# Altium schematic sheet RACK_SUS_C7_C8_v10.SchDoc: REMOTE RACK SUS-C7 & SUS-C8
size C; Engineer: L. Sanchez; Organization: LIGO Laboratory; Address1: California Institute of Technology; Address2: Massachusetts Institute of Technology; DocumentNumber: D1002740; Revision: v10; SheetNumber: 8; SheetTotal: 8
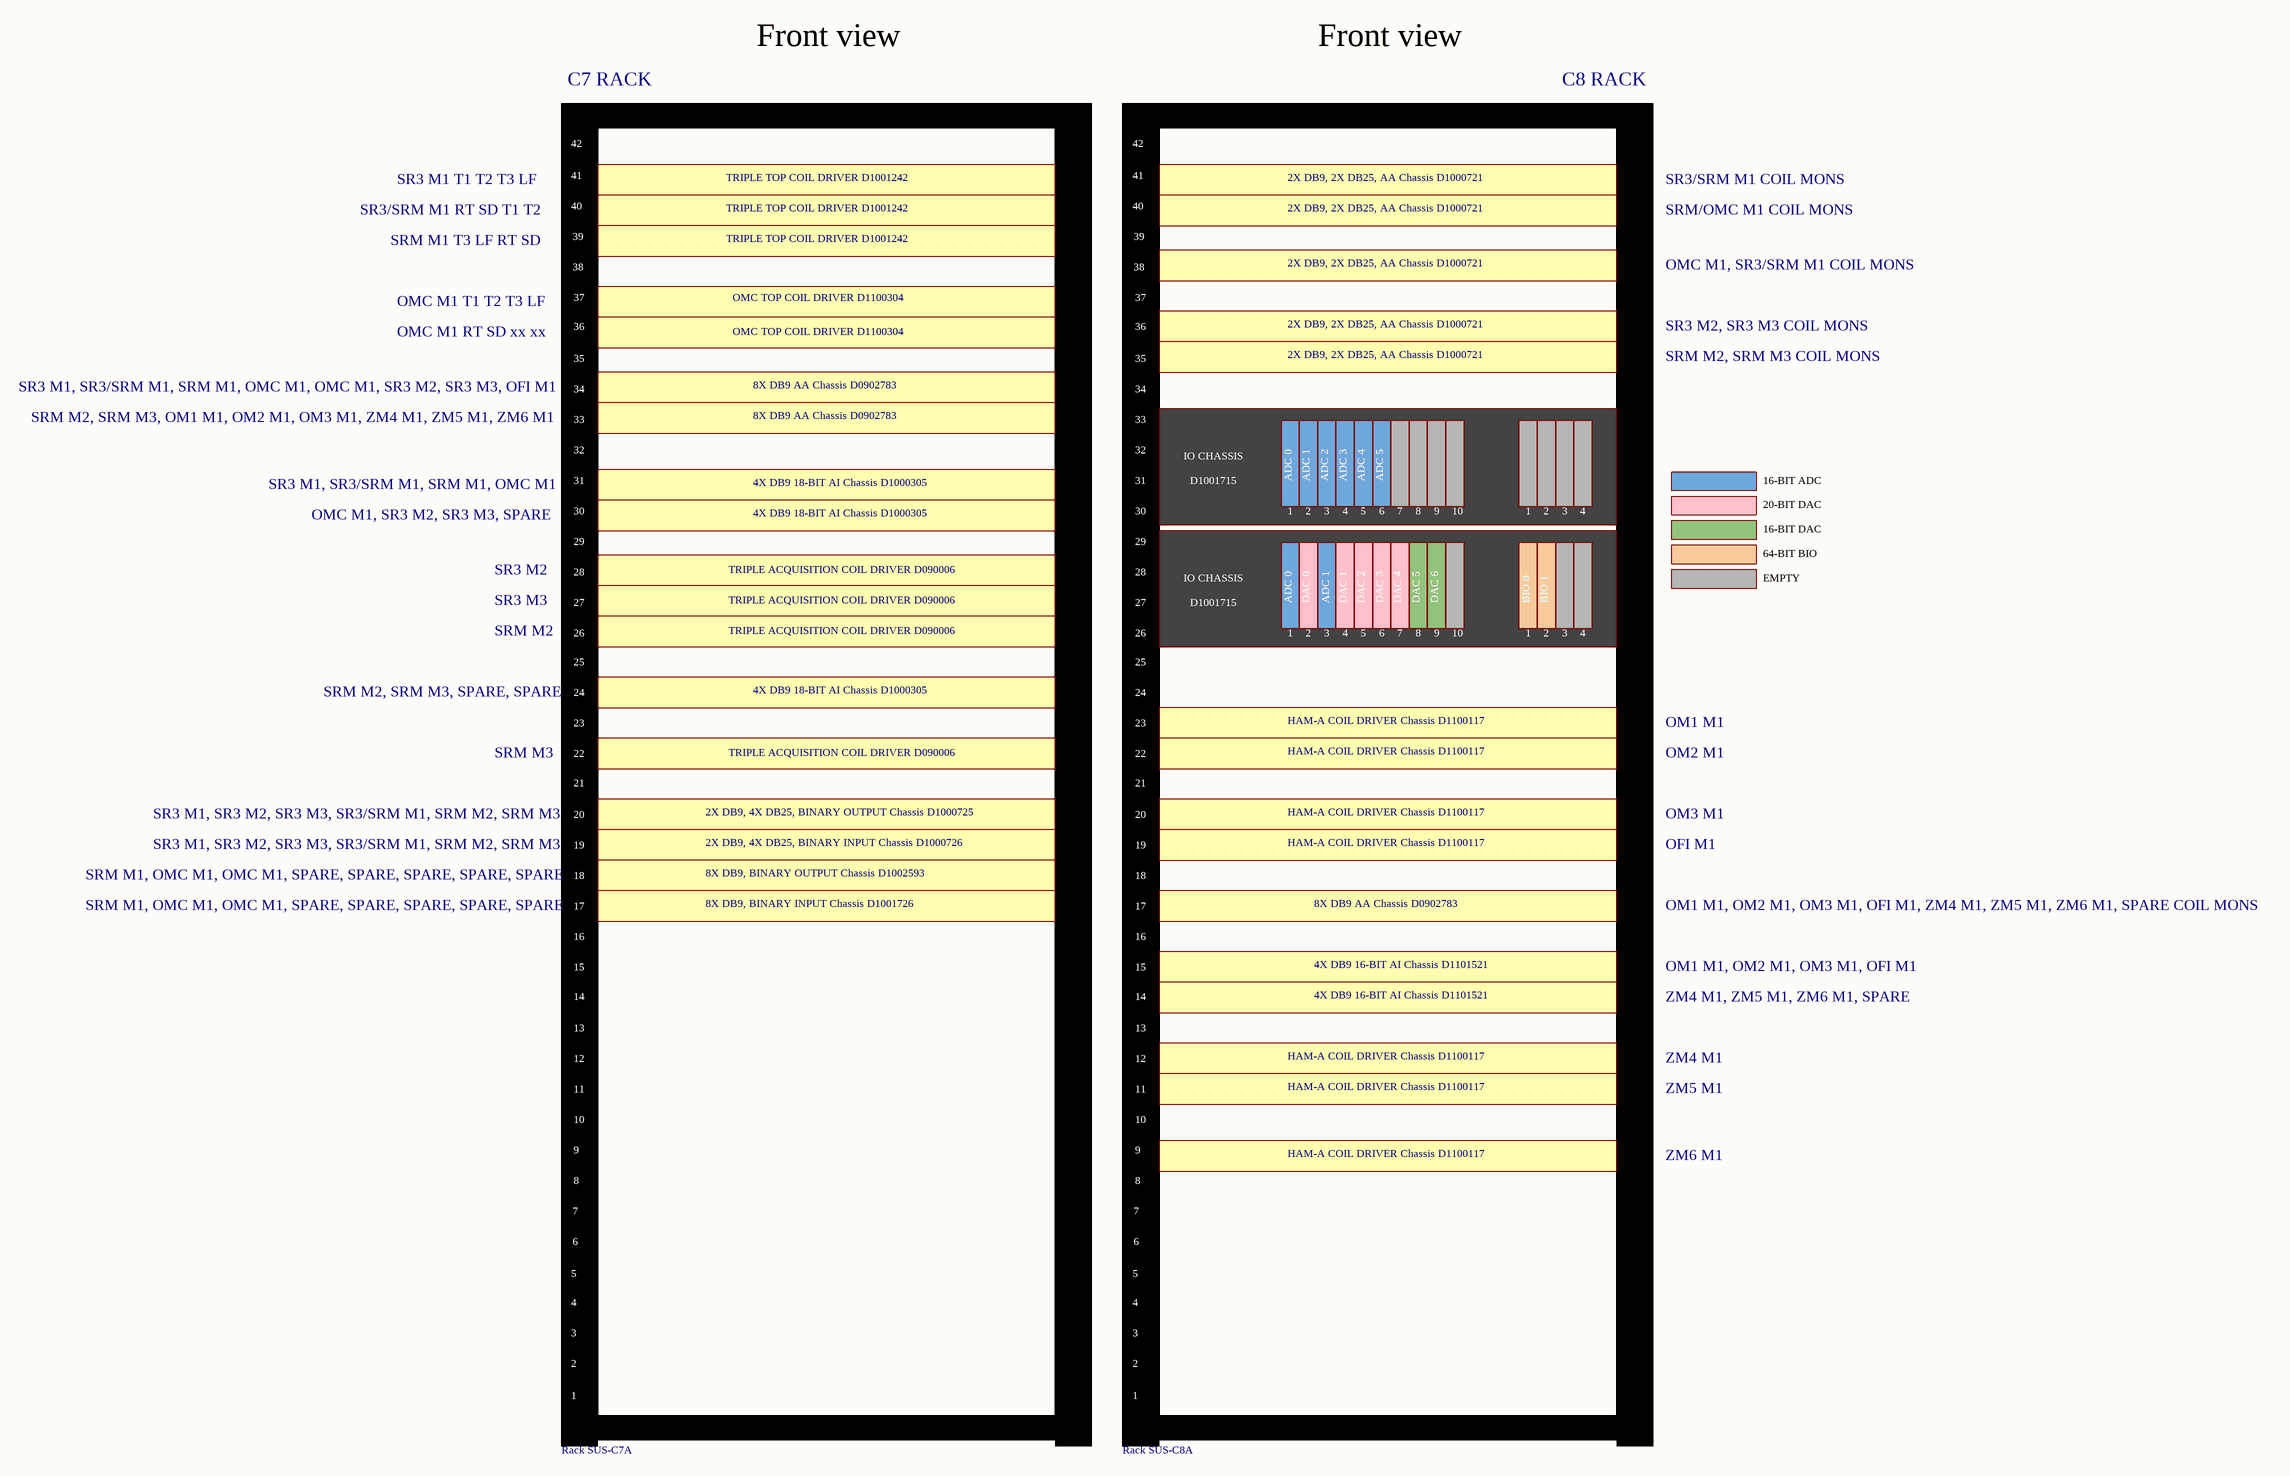
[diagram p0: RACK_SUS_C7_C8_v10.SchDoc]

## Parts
Rack_SUS-C7  1U  Rack 42 pos  (value not drawn)  (part A of 2)
Rack_SUS-C8  1U  Rack 42 pos  (value not drawn)  (part A of 2)

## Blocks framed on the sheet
2X DB9, 4X DB25, BINARY OUTPUT Chassis D1000725: Rack_SUS-C7
HAM-A COIL DRIVER Chassis D1100117: Rack_SUS-C8

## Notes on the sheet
- Front view
- C7 RACK
- C8 RACK
- SR3 M1 T1 T2 T3 LF
- TRIPLE TOP COIL DRIVER D1001242
- 2X DB9, 2X DB25, AA Chassis D1000721
- SR3/SRM M1 COIL MONS
- SR3/SRM M1 RT SD T1 T2
- SRM M1 T3 LF RT SD
- SRM/OMC M1 COIL MONS
- OMC M1 T1 T2 T3 LF
- OMC TOP COIL DRIVER D1100304
- OMC M1, SR3/SRM M1 COIL MONS
- OMC M1 RT SD xx xx
- SR3 M2, SR3 M3 COIL MONS
- SRM M2, SRM M3 COIL MONS
- SR3 M1, SR3/SRM M1, SRM M1, OMC M1, OMC M1, SR3 M2, SR3 M3, OFI M1
- SRM M2, SRM M3, OM1 M1, OM2 M1, OM3 M1, ZM4 M1, ZM5 M1, ZM6 M1
- 8X DB9 AA Chassis D0902783
- SR3 M1, SR3/SRM M1, SRM M1, OMC M1
- 4X DB9 18-BIT AI Chassis D1000305
- IO CHASSIS
- D1001715
- ADC 0
- ADC 1
- ADC 2
- ADC 3
- ADC 4
- ADC 5
- 16-BIT ADC
- OMC M1, SR3 M2, SR3 M3, SPARE
- 1
- 2
- 3
- 4
- 5
- 6
- 7
- 8
- 9
- 10
- 20-BIT DAC
- 16-BIT DAC
- 64-BIT BIO
- SR3 M2
- SR3 M3
- TRIPLE ACQUISITION COIL DRIVER D090006
- DAC 0
- DAC 1
- DAC 2
- DAC 3
- DAC 4
- DAC 5
- DAC 6
- BIO 0
- BIO 1
- EMPTY
- SRM M2
- SRM M2, SRM M3, SPARE, SPARE
- HAM-A COIL DRIVER Chassis D1100117
- OM1 M1
- SRM M3
- OM2 M1
- SR3 M1, SR3 M2, SR3 M3, SR3/SRM M1, SRM M2, SRM M3
- (near Rack_SUS-C7) 2X DB9, 4X DB25, BINARY INPUT Chassis D1000726
- (near Rack_SUS-C8) HAM-A COIL DRIVER Chassis D1100117
- OM3 M1
- OFI M1
- SRM M1, OMC M1, OMC M1, SPARE, SPARE, SPARE, SPARE, SPARE
- 8X DB9, BINARY OUTPUT Chassis D1002593
- 8X DB9, BINARY INPUT Chassis D1001726
- OM1 M1, OM2 M1, OM3 M1, OFI M1, ZM4 M1, ZM5 M1, ZM6 M1, SPARE COIL MONS
- 4X DB9 16-BIT AI Chassis D1101521
- OM1 M1, OM2 M1, OM3 M1, OFI M1
- ZM4 M1, ZM5 M1, ZM6 M1, SPARE
- ZM4 M1
- ZM5 M1
- ZM6 M1

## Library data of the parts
Rack_SUS-C7 Rack_SUS-C8 = RACK_42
